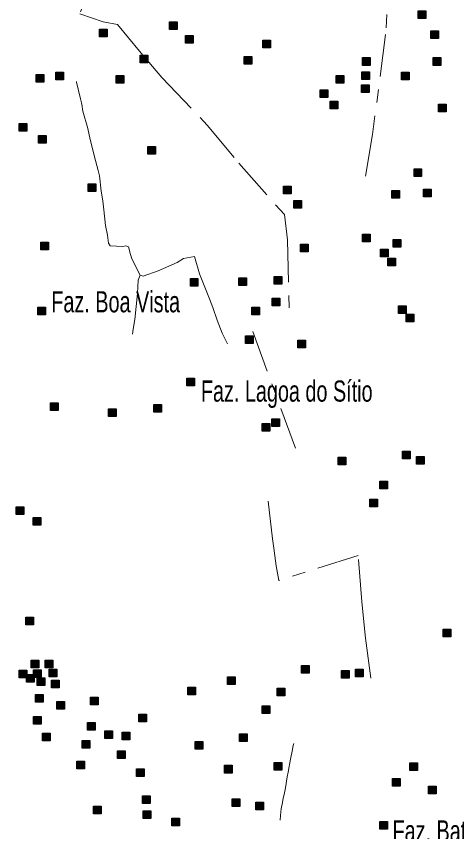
# Model space of a CAD drawing. Extents: x 445.4 to 500, y 8728.7 to 8784.
# Drawn here: x 480.51 to 483.85, y 8757.8 to 8763.96 of the extents above; entities that cross this region are included whole.
import ezdxf

# ---------------------------------------------------------------- set-up
doc = ezdxf.new("R2010")
doc.units = 0
doc.header["$LTSCALE"] = 0.064
doc.linetypes.add('DOT_DASHED', pattern=[7.7, 5, -1.2, 0.3, -1.2])
doc.layers.add('2', color=7, linetype='Continuous', lineweight=25)
doc.layers.add('22', color=7, linetype='DOT_DASHED', lineweight=13)
doc.layers.add('61', color=7, linetype='Continuous')

msp = doc.modelspace()

# ---------------------------------------------------------------- hatches: boundary and pattern name
at = {"layer": '2'}
for points in [[(483.5536, 8764.0015), (483.6116, 8764.0015), (483.6116, 8763.9435), (483.5536, 8763.9435)], [(481.6712, 8763.92), (481.7292, 8763.92), (481.7292, 8763.862), (481.6712, 8763.862)], [(481.143, 8763.8651), (481.201, 8763.8651), (481.201, 8763.8071), (481.143, 8763.8071)], [(483.6486, 8763.8521), (483.7066, 8763.8521), (483.7066, 8763.7941), (483.6486, 8763.7941)], [(481.7934, 8763.8159), (481.8514, 8763.8159), (481.8514, 8763.7579), (481.7934, 8763.7579)], [(482.3771, 8763.7797), (482.4351, 8763.7797), (482.4351, 8763.7217), (482.3771, 8763.7217)], [(481.4495, 8763.6665), (481.5075, 8763.6665), (481.5075, 8763.6085), (481.4495, 8763.6085)], [(482.2368, 8763.6574), (482.2948, 8763.6574), (482.2948, 8763.5994), (482.2368, 8763.5994)], [(483.1328, 8763.6484), (483.1908, 8763.6484), (483.1908, 8763.5904), (483.1328, 8763.5904)], [(483.6667, 8763.6484), (483.7247, 8763.6484), (483.7247, 8763.5904), (483.6667, 8763.5904)], [(480.6621, 8763.5214), (480.7201, 8763.5214), (480.7201, 8763.4634), (480.6621, 8763.4634)], [(480.8114, 8763.5395), (480.8694, 8763.5395), (480.8694, 8763.4815), (480.8114, 8763.4815)], [(481.2685, 8763.5143), (481.3265, 8763.5143), (481.3265, 8763.4563), (481.2685, 8763.4563)], [(482.9337, 8763.5143), (482.9917, 8763.5143), (482.9917, 8763.4563), (482.9337, 8763.4563)], [(483.1282, 8763.5415), (483.1862, 8763.5415), (483.1862, 8763.4835), (483.1282, 8763.4835)], [(483.4269, 8763.5391), (483.4849, 8763.5391), (483.4849, 8763.4811), (483.4269, 8763.4811)], [(482.8115, 8763.4056), (482.8695, 8763.4056), (482.8695, 8763.3476), (482.8115, 8763.3476)], [(483.1237, 8763.4419), (483.1817, 8763.4419), (483.1817, 8763.3839), (483.1237, 8763.3839)], [(482.8884, 8763.3196), (482.9464, 8763.3196), (482.9464, 8763.2616), (482.8884, 8763.2616)], [(483.7074, 8763.297), (483.7654, 8763.297), (483.7654, 8763.239), (483.7074, 8763.239)], [(480.5354, 8763.1501), (480.5934, 8763.1501), (480.5934, 8763.0921), (480.5354, 8763.0921)], [(480.6802, 8763.0596), (480.7382, 8763.0596), (480.7382, 8763.0016), (480.6802, 8763.0016)], [(481.5083, 8762.9755), (481.5663, 8762.9755), (481.5663, 8762.9175), (481.5083, 8762.9175)], [(483.5219, 8762.808), (483.5799, 8762.808), (483.5799, 8762.75), (483.5219, 8762.75)], [(481.0558, 8762.6948), (481.1138, 8762.6948), (481.1138, 8762.6368), (481.0558, 8762.6368)], [(482.5355, 8762.6767), (482.5935, 8762.6767), (482.5935, 8762.6187), (482.5355, 8762.6187)], [(483.5943, 8762.6541), (483.6523, 8762.6541), (483.6523, 8762.5961), (483.5943, 8762.5961)], [(483.3545, 8762.645), (483.4125, 8762.645), (483.4125, 8762.587), (483.3545, 8762.587)], [(482.6124, 8762.5681), (482.6704, 8762.5681), (482.6704, 8762.5101), (482.6124, 8762.5101)], [(483.1328, 8762.3145), (483.1908, 8762.3145), (483.1908, 8762.2565), (483.1328, 8762.2565)], [(480.6983, 8762.2537), (480.7563, 8762.2537), (480.7563, 8762.1957), (480.6983, 8762.1957)], [(482.6622, 8762.2376), (482.7202, 8762.2376), (482.7202, 8762.1796), (482.6622, 8762.1796)], [(483.3635, 8762.2738), (483.4215, 8762.2738), (483.4215, 8762.2158), (483.3635, 8762.2158)], [(483.2685, 8762.2013), (483.3265, 8762.2013), (483.3265, 8762.1433), (483.2685, 8762.1433)], [(483.3228, 8762.1334), (483.3808, 8762.1334), (483.3808, 8762.0754), (483.3228, 8762.0754)], [(481.8296, 8761.9795), (481.8876, 8761.9795), (481.8876, 8761.9215), (481.8296, 8761.9215)], [(482.1961, 8761.984), (482.2541, 8761.984), (482.2541, 8761.926), (482.1961, 8761.926)], [(482.4641, 8761.9945), (482.5221, 8761.9945), (482.5221, 8761.9365), (482.4641, 8761.9365)], [(482.4495, 8761.8301), (482.5075, 8761.8301), (482.5075, 8761.7721), (482.4495, 8761.7721)], [(480.6757, 8761.763), (480.7337, 8761.763), (480.7337, 8761.705), (480.6757, 8761.705)], [(482.2944, 8761.7629), (482.3524, 8761.7629), (482.3524, 8761.7049), (482.2944, 8761.7049)], [(483.4043, 8761.7712), (483.4623, 8761.7712), (483.4623, 8761.7132), (483.4043, 8761.7132)], [(483.4631, 8761.7079), (483.5211, 8761.7079), (483.5211, 8761.6499), (483.4631, 8761.6499)], [(482.2459, 8761.5449), (482.3039, 8761.5449), (482.3039, 8761.4869), (482.2459, 8761.4869)], [(482.6441, 8761.5132), (482.7021, 8761.5132), (482.7021, 8761.4552), (482.6441, 8761.4552)], [(481.8031, 8761.2258), (481.8611, 8761.2258), (481.8611, 8761.1678), (481.8031, 8761.1678)], [(480.7707, 8761.0386), (480.8287, 8761.0386), (480.8287, 8760.9806), (480.7707, 8760.9806)], [(481.2096, 8760.9943), (481.2676, 8760.9943), (481.2676, 8760.9363), (481.2096, 8760.9363)], [(481.5535, 8761.026), (481.6115, 8761.026), (481.6115, 8760.968), (481.5535, 8760.968)], [(482.3726, 8760.8811), (482.4306, 8760.8811), (482.4306, 8760.8231), (482.3726, 8760.8231)], [(482.445, 8760.9173), (482.503, 8760.9173), (482.503, 8760.8593), (482.445, 8760.8593)], [(482.9472, 8760.6276), (483.0052, 8760.6276), (483.0052, 8760.5696), (482.9472, 8760.5696)], [(483.4359, 8760.6728), (483.4939, 8760.6728), (483.4939, 8760.6148), (483.4359, 8760.6148)], [(483.54, 8760.6321), (483.598, 8760.6321), (483.598, 8760.5741), (483.54, 8760.5741)], [(483.264, 8760.4465), (483.322, 8760.4465), (483.322, 8760.3885), (483.264, 8760.3885)], [(483.1871, 8760.3106), (483.2451, 8760.3106), (483.2451, 8760.2526), (483.1871, 8760.2526)], [(480.5128, 8760.2526), (480.5708, 8760.2526), (480.5708, 8760.1946), (480.5128, 8760.1946)], [(480.6395, 8760.1711), (480.6975, 8760.1711), (480.6975, 8760.1131), (480.6395, 8760.1131)], [(480.5852, 8759.4178), (480.6432, 8759.4178), (480.6432, 8759.3598), (480.5852, 8759.3598)], [(483.7436, 8759.3282), (483.8016, 8759.3282), (483.8016, 8759.2702), (483.7436, 8759.2702)], [(480.6259, 8759.0918), (480.6839, 8759.0918), (480.6839, 8759.0338), (480.6259, 8759.0338)], [(480.73, 8759.0918), (480.788, 8759.0918), (480.788, 8759.0338), (480.73, 8759.0338)], [(480.5354, 8759.0184), (480.5934, 8759.0184), (480.5934, 8758.9604), (480.5354, 8758.9604)], [(480.644, 8759.0193), (480.702, 8759.0193), (480.702, 8758.9613), (480.644, 8758.9613)], [(480.7617, 8759.0239), (480.8197, 8759.0239), (480.8197, 8758.9659), (480.7617, 8758.9659)], [(482.6712, 8759.052), (482.7292, 8759.052), (482.7292, 8758.994), (482.6712, 8758.994)], [(482.9744, 8759.0158), (483.0324, 8759.0158), (483.0324, 8758.9578), (482.9744, 8758.9578)], [(483.0785, 8759.0248), (483.1365, 8759.0248), (483.1365, 8758.9668), (483.0785, 8758.9668)], [(480.5908, 8758.9843), (480.6488, 8758.9843), (480.6488, 8758.9263), (480.5908, 8758.9263)], [(480.6712, 8758.9605), (480.7292, 8758.9605), (480.7292, 8758.9025), (480.6712, 8758.9025)], [(482.1101, 8758.966), (482.1681, 8758.966), (482.1681, 8758.908), (482.1101, 8758.908)], [(480.7798, 8758.9424), (480.8378, 8758.9424), (480.8378, 8758.8844), (480.7798, 8758.8844)], [(480.6576, 8758.8337), (480.7156, 8758.8337), (480.7156, 8758.7757), (480.6576, 8758.7757)], [(481.8115, 8758.889), (481.8695, 8758.889), (481.8695, 8758.831), (481.8115, 8758.831)], [(482.4857, 8758.88), (482.5437, 8758.88), (482.5437, 8758.822), (482.4857, 8758.822)], [(480.8205, 8758.7812), (480.8785, 8758.7812), (480.8785, 8758.7232), (480.8205, 8758.7232)], [(481.0739, 8758.8121), (481.1319, 8758.8121), (481.1319, 8758.7541), (481.0739, 8758.7541)], [(482.3726, 8758.7487), (482.4306, 8758.7487), (482.4306, 8758.6907), (482.3726, 8758.6907)], [(480.644, 8758.668), (480.702, 8758.668), (480.702, 8758.61), (480.644, 8758.61)], [(481.4404, 8758.6853), (481.4984, 8758.6853), (481.4984, 8758.6273), (481.4404, 8758.6273)], [(481.0513, 8758.6219), (481.1093, 8758.6219), (481.1093, 8758.5639), (481.0513, 8758.5639)], [(480.7119, 8758.5412), (480.7699, 8758.5412), (480.7699, 8758.4832), (480.7119, 8758.4832)], [(481.1825, 8758.5585), (481.2405, 8758.5585), (481.2405, 8758.5005), (481.1825, 8758.5005)], [(481.3137, 8758.5495), (481.3717, 8758.5495), (481.3717, 8758.4915), (481.3137, 8758.4915)], [(482.2006, 8758.5359), (482.2586, 8758.5359), (482.2586, 8758.4779), (482.2006, 8758.4779)], [(481.0105, 8758.4861), (481.0685, 8758.4861), (481.0685, 8758.4281), (481.0105, 8758.4281)], [(481.8658, 8758.4788), (481.9238, 8758.4788), (481.9238, 8758.4208), (481.8658, 8758.4208)], [(481.2775, 8758.4064), (481.3355, 8758.4064), (481.3355, 8758.3484), (481.2775, 8758.3484)], [(480.9698, 8758.3294), (481.0278, 8758.3294), (481.0278, 8758.2714), (480.9698, 8758.2714)], [(482.0875, 8758.2977), (482.1455, 8758.2977), (482.1455, 8758.2397), (482.0875, 8758.2397)], [(482.4631, 8758.3203), (482.5211, 8758.3203), (482.5211, 8758.2623), (482.4631, 8758.2623)], [(483.4902, 8758.3158), (483.5482, 8758.3158), (483.5482, 8758.2578), (483.4902, 8758.2578)], [(481.4223, 8758.2705), (481.4803, 8758.2705), (481.4803, 8758.2125), (481.4223, 8758.2125)], [(483.359, 8758.1981), (483.417, 8758.1981), (483.417, 8758.1401), (483.359, 8758.1401)], [(483.6305, 8758.1392), (483.6885, 8758.1392), (483.6885, 8758.0812), (483.6305, 8758.0812)], [(481.4676, 8758.0668), (481.5256, 8758.0668), (481.5256, 8758.0088), (481.4676, 8758.0088)], [(482.1463, 8758.0442), (482.2043, 8758.0442), (482.2043, 8757.9862), (482.1463, 8757.9862)], [(481.0965, 8757.9898), (481.1545, 8757.9898), (481.1545, 8757.9318), (481.0965, 8757.9318)], [(482.3257, 8758.0192), (482.3837, 8758.0192), (482.3837, 8757.9612), (482.3257, 8757.9612)], [(481.4721, 8757.9536), (481.5301, 8757.9536), (481.5301, 8757.8956), (481.4721, 8757.8956)], [(481.6893, 8757.8993), (481.7473, 8757.8993), (481.7473, 8757.8413), (481.6893, 8757.8413)], [(483.264, 8757.8721), (483.322, 8757.8721), (483.322, 8757.8141), (483.264, 8757.8141)]]:
    msp.add_hatch(color=256, dxfattribs=at).paths.add_polyline_path(points)

# ---------------------------------------------------------------- linework, layer by layer
for points in [[(483.5536, 8764.0015), (483.6116, 8764.0015), (483.6116, 8763.9435), (483.5536, 8763.9435)], [(481.6712, 8763.92), (481.7292, 8763.92), (481.7292, 8763.862), (481.6712, 8763.862)], [(481.143, 8763.8651), (481.201, 8763.8651), (481.201, 8763.8071), (481.143, 8763.8071)], [(483.6486, 8763.8521), (483.7066, 8763.8521), (483.7066, 8763.7941), (483.6486, 8763.7941)], [(481.7934, 8763.8159), (481.8514, 8763.8159), (481.8514, 8763.7579), (481.7934, 8763.7579)], [(482.3771, 8763.7797), (482.4351, 8763.7797), (482.4351, 8763.7217), (482.3771, 8763.7217)], [(481.4495, 8763.6665), (481.5075, 8763.6665), (481.5075, 8763.6085), (481.4495, 8763.6085)], [(482.2368, 8763.6574), (482.2948, 8763.6574), (482.2948, 8763.5994), (482.2368, 8763.5994)], [(483.1328, 8763.6484), (483.1908, 8763.6484), (483.1908, 8763.5904), (483.1328, 8763.5904)], [(483.6667, 8763.6484), (483.7247, 8763.6484), (483.7247, 8763.5904), (483.6667, 8763.5904)], [(480.6621, 8763.5214), (480.7201, 8763.5214), (480.7201, 8763.4634), (480.6621, 8763.4634)], [(480.8114, 8763.5395), (480.8694, 8763.5395), (480.8694, 8763.4815), (480.8114, 8763.4815)], [(481.2685, 8763.5143), (481.3265, 8763.5143), (481.3265, 8763.4563), (481.2685, 8763.4563)], [(482.9337, 8763.5143), (482.9917, 8763.5143), (482.9917, 8763.4563), (482.9337, 8763.4563)], [(483.1282, 8763.5415), (483.1862, 8763.5415), (483.1862, 8763.4835), (483.1282, 8763.4835)], [(483.4269, 8763.5391), (483.4849, 8763.5391), (483.4849, 8763.4811), (483.4269, 8763.4811)], [(482.8115, 8763.4056), (482.8695, 8763.4056), (482.8695, 8763.3476), (482.8115, 8763.3476)], [(483.1237, 8763.4419), (483.1817, 8763.4419), (483.1817, 8763.3839), (483.1237, 8763.3839)], [(482.8884, 8763.3196), (482.9464, 8763.3196), (482.9464, 8763.2616), (482.8884, 8763.2616)], [(483.7074, 8763.297), (483.7654, 8763.297), (483.7654, 8763.239), (483.7074, 8763.239)], [(480.5354, 8763.1501), (480.5934, 8763.1501), (480.5934, 8763.0921), (480.5354, 8763.0921)], [(480.6802, 8763.0596), (480.7382, 8763.0596), (480.7382, 8763.0016), (480.6802, 8763.0016)], [(481.5083, 8762.9755), (481.5663, 8762.9755), (481.5663, 8762.9175), (481.5083, 8762.9175)], [(483.5219, 8762.808), (483.5799, 8762.808), (483.5799, 8762.75), (483.5219, 8762.75)], [(481.0558, 8762.6948), (481.1138, 8762.6948), (481.1138, 8762.6368), (481.0558, 8762.6368)], [(482.5355, 8762.6767), (482.5935, 8762.6767), (482.5935, 8762.6187), (482.5355, 8762.6187)], [(483.5943, 8762.6541), (483.6523, 8762.6541), (483.6523, 8762.5961), (483.5943, 8762.5961)], [(483.3545, 8762.645), (483.4125, 8762.645), (483.4125, 8762.587), (483.3545, 8762.587)], [(482.6124, 8762.5681), (482.6704, 8762.5681), (482.6704, 8762.5101), (482.6124, 8762.5101)], [(483.1328, 8762.3145), (483.1908, 8762.3145), (483.1908, 8762.2565), (483.1328, 8762.2565)], [(480.6983, 8762.2537), (480.7563, 8762.2537), (480.7563, 8762.1957), (480.6983, 8762.1957)], [(482.6622, 8762.2376), (482.7202, 8762.2376), (482.7202, 8762.1796), (482.6622, 8762.1796)], [(483.3635, 8762.2738), (483.4215, 8762.2738), (483.4215, 8762.2158), (483.3635, 8762.2158)], [(483.2685, 8762.2013), (483.3265, 8762.2013), (483.3265, 8762.1433), (483.2685, 8762.1433)], [(483.3228, 8762.1334), (483.3808, 8762.1334), (483.3808, 8762.0754), (483.3228, 8762.0754)], [(481.8296, 8761.9795), (481.8876, 8761.9795), (481.8876, 8761.9215), (481.8296, 8761.9215)], [(482.1961, 8761.984), (482.2541, 8761.984), (482.2541, 8761.926), (482.1961, 8761.926)], [(482.4641, 8761.9945), (482.5221, 8761.9945), (482.5221, 8761.9365), (482.4641, 8761.9365)], [(482.4495, 8761.8301), (482.5075, 8761.8301), (482.5075, 8761.7721), (482.4495, 8761.7721)], [(480.6757, 8761.763), (480.7337, 8761.763), (480.7337, 8761.705), (480.6757, 8761.705)], [(482.2944, 8761.7629), (482.3524, 8761.7629), (482.3524, 8761.7049), (482.2944, 8761.7049)], [(483.4043, 8761.7712), (483.4623, 8761.7712), (483.4623, 8761.7132), (483.4043, 8761.7132)], [(483.4631, 8761.7079), (483.5211, 8761.7079), (483.5211, 8761.6499), (483.4631, 8761.6499)], [(482.2459, 8761.5449), (482.3039, 8761.5449), (482.3039, 8761.4869), (482.2459, 8761.4869)], [(482.6441, 8761.5132), (482.7021, 8761.5132), (482.7021, 8761.4552), (482.6441, 8761.4552)], [(481.8031, 8761.2258), (481.8611, 8761.2258), (481.8611, 8761.1678), (481.8031, 8761.1678)], [(480.7707, 8761.0386), (480.8287, 8761.0386), (480.8287, 8760.9806), (480.7707, 8760.9806)], [(481.2096, 8760.9943), (481.2676, 8760.9943), (481.2676, 8760.9363), (481.2096, 8760.9363)], [(481.5535, 8761.026), (481.6115, 8761.026), (481.6115, 8760.968), (481.5535, 8760.968)], [(482.3726, 8760.8811), (482.4306, 8760.8811), (482.4306, 8760.8231), (482.3726, 8760.8231)], [(482.445, 8760.9173), (482.503, 8760.9173), (482.503, 8760.8593), (482.445, 8760.8593)], [(482.9472, 8760.6276), (483.0052, 8760.6276), (483.0052, 8760.5696), (482.9472, 8760.5696)], [(483.4359, 8760.6728), (483.4939, 8760.6728), (483.4939, 8760.6148), (483.4359, 8760.6148)], [(483.54, 8760.6321), (483.598, 8760.6321), (483.598, 8760.5741), (483.54, 8760.5741)], [(483.264, 8760.4465), (483.322, 8760.4465), (483.322, 8760.3885), (483.264, 8760.3885)], [(483.1871, 8760.3106), (483.2451, 8760.3106), (483.2451, 8760.2526), (483.1871, 8760.2526)], [(480.5128, 8760.2526), (480.5708, 8760.2526), (480.5708, 8760.1946), (480.5128, 8760.1946)], [(480.6395, 8760.1711), (480.6975, 8760.1711), (480.6975, 8760.1131), (480.6395, 8760.1131)], [(480.5852, 8759.4178), (480.6432, 8759.4178), (480.6432, 8759.3598), (480.5852, 8759.3598)], [(483.7436, 8759.3282), (483.8016, 8759.3282), (483.8016, 8759.2702), (483.7436, 8759.2702)], [(480.6259, 8759.0918), (480.6839, 8759.0918), (480.6839, 8759.0338), (480.6259, 8759.0338)], [(480.73, 8759.0918), (480.788, 8759.0918), (480.788, 8759.0338), (480.73, 8759.0338)], [(480.5354, 8759.0184), (480.5934, 8759.0184), (480.5934, 8758.9604), (480.5354, 8758.9604)], [(480.644, 8759.0193), (480.702, 8759.0193), (480.702, 8758.9613), (480.644, 8758.9613)], [(480.7617, 8759.0239), (480.8197, 8759.0239), (480.8197, 8758.9659), (480.7617, 8758.9659)], [(482.6712, 8759.052), (482.7292, 8759.052), (482.7292, 8758.994), (482.6712, 8758.994)], [(482.9744, 8759.0158), (483.0324, 8759.0158), (483.0324, 8758.9578), (482.9744, 8758.9578)], [(483.0785, 8759.0248), (483.1365, 8759.0248), (483.1365, 8758.9668), (483.0785, 8758.9668)], [(480.5908, 8758.9843), (480.6488, 8758.9843), (480.6488, 8758.9263), (480.5908, 8758.9263)], [(480.6712, 8758.9605), (480.7292, 8758.9605), (480.7292, 8758.9025), (480.6712, 8758.9025)], [(482.1101, 8758.966), (482.1681, 8758.966), (482.1681, 8758.908), (482.1101, 8758.908)], [(480.7798, 8758.9424), (480.8378, 8758.9424), (480.8378, 8758.8844), (480.7798, 8758.8844)], [(480.6576, 8758.8337), (480.7156, 8758.8337), (480.7156, 8758.7757), (480.6576, 8758.7757)], [(481.8115, 8758.889), (481.8695, 8758.889), (481.8695, 8758.831), (481.8115, 8758.831)], [(482.4857, 8758.88), (482.5437, 8758.88), (482.5437, 8758.822), (482.4857, 8758.822)], [(480.8205, 8758.7812), (480.8785, 8758.7812), (480.8785, 8758.7232), (480.8205, 8758.7232)], [(481.0739, 8758.8121), (481.1319, 8758.8121), (481.1319, 8758.7541), (481.0739, 8758.7541)], [(482.3726, 8758.7487), (482.4306, 8758.7487), (482.4306, 8758.6907), (482.3726, 8758.6907)], [(480.644, 8758.668), (480.702, 8758.668), (480.702, 8758.61), (480.644, 8758.61)], [(481.4404, 8758.6853), (481.4984, 8758.6853), (481.4984, 8758.6273), (481.4404, 8758.6273)], [(481.0513, 8758.6219), (481.1093, 8758.6219), (481.1093, 8758.5639), (481.0513, 8758.5639)], [(480.7119, 8758.5412), (480.7699, 8758.5412), (480.7699, 8758.4832), (480.7119, 8758.4832)], [(481.1825, 8758.5585), (481.2405, 8758.5585), (481.2405, 8758.5005), (481.1825, 8758.5005)], [(481.3137, 8758.5495), (481.3717, 8758.5495), (481.3717, 8758.4915), (481.3137, 8758.4915)], [(482.2006, 8758.5359), (482.2586, 8758.5359), (482.2586, 8758.4779), (482.2006, 8758.4779)], [(481.0105, 8758.4861), (481.0685, 8758.4861), (481.0685, 8758.4281), (481.0105, 8758.4281)], [(481.8658, 8758.4788), (481.9238, 8758.4788), (481.9238, 8758.4208), (481.8658, 8758.4208)], [(481.2775, 8758.4064), (481.3355, 8758.4064), (481.3355, 8758.3484), (481.2775, 8758.3484)], [(480.9698, 8758.3294), (481.0278, 8758.3294), (481.0278, 8758.2714), (480.9698, 8758.2714)], [(482.0875, 8758.2977), (482.1455, 8758.2977), (482.1455, 8758.2397), (482.0875, 8758.2397)], [(482.4631, 8758.3203), (482.5211, 8758.3203), (482.5211, 8758.2623), (482.4631, 8758.2623)], [(483.4902, 8758.3158), (483.5482, 8758.3158), (483.5482, 8758.2578), (483.4902, 8758.2578)], [(481.4223, 8758.2705), (481.4803, 8758.2705), (481.4803, 8758.2125), (481.4223, 8758.2125)], [(483.359, 8758.1981), (483.417, 8758.1981), (483.417, 8758.1401), (483.359, 8758.1401)], [(483.6305, 8758.1392), (483.6885, 8758.1392), (483.6885, 8758.0812), (483.6305, 8758.0812)], [(481.4676, 8758.0668), (481.5256, 8758.0668), (481.5256, 8758.0088), (481.4676, 8758.0088)], [(482.1463, 8758.0442), (482.2043, 8758.0442), (482.2043, 8757.9862), (482.1463, 8757.9862)], [(481.0965, 8757.9898), (481.1545, 8757.9898), (481.1545, 8757.9318), (481.0965, 8757.9318)], [(482.3257, 8758.0192), (482.3837, 8758.0192), (482.3837, 8757.9612), (482.3257, 8757.9612)], [(481.4721, 8757.9536), (481.5301, 8757.9536), (481.5301, 8757.8956), (481.4721, 8757.8956)], [(481.6893, 8757.8993), (481.7473, 8757.8993), (481.7473, 8757.8413), (481.6893, 8757.8413)], [(483.264, 8757.8721), (483.322, 8757.8721), (483.322, 8757.8141), (483.264, 8757.8141)]]:
    msp.add_lwpolyline(points, close=True, dxfattribs=at)
at = {"layer": '22'}
msp.add_line((482.6254, 8760.6949), (482.2954, 8761.594), dxfattribs=at)
for points in [[(483.17, 8764.8294), (483.3433, 8764.3939), (483.3075, 8763.8242), (483.208, 8763.0675), (483.1399, 8762.6614)], [(481.185, 8764.48), (480.9932, 8763.9797), (481.1704, 8763.9201), (481.279, 8763.8984), (481.4448, 8763.6968), (481.6132, 8763.4981), (481.9577, 8763.1388), (482.197, 8762.8515), (482.5414, 8762.4616), (482.5644, 8762.2705), (482.5773, 8761.756)], [(481.0156, 8763.2428), (481.0129, 8763.2556), (481.011, 8763.2825), (481.0072, 8763.3075), (480.9995, 8763.3383), (480.9687, 8763.4634), (480.9679, 8763.4678)], [(481.4512, 8762.0028), (481.3874, 8762.1267), (481.3761, 8762.1605), (481.3611, 8762.2169), (481.3423, 8762.2244), (481.3197, 8762.2207), (481.2221, 8762.2244), (481.2108, 8762.247), (481.2033, 8762.3071), (481.1882, 8762.3786), (481.1755, 8762.4988), (481.1669, 8762.5662), (481.1548, 8762.638), (481.1427, 8762.7555), (481.1319, 8762.7959), (481.1131, 8762.8711), (481.0726, 8763.0293), (481.053, 8763.1117), (481.0156, 8763.2428)], [(481.4512, 8762.0028), (481.4738, 8761.9951), (481.5865, 8762.0364), (481.7293, 8762.1003), (481.7782, 8762.1304), (481.8608, 8762.1455), (481.8984, 8762.0139), (481.9735, 8761.8259), (481.9998, 8761.7582), (482.0337, 8761.6642), (482.0712, 8761.5665), (482.1109, 8761.4839)], [(481.4512, 8762.0028), (481.4357, 8761.9668), (481.43, 8761.8644), (481.4206, 8761.7677), (481.4092, 8761.6691), (481.3978, 8761.5951), (481.3931, 8761.5578)], [(483.195, 8758.9577), (483.1558, 8759.2593), (483.1273, 8759.5344), (483.0988, 8759.8855), (482.5002, 8759.6958), (482.4778, 8759.805), (482.4604, 8759.9402), (482.4502, 8760.0098), (482.4173, 8760.2957)], [(482.5085, 8757.8824), (482.5106, 8757.9173), (482.5174, 8757.969), (482.5271, 8758.0158), (482.5324, 8758.0485), (482.5388, 8758.0765), (482.5485, 8758.1287), (482.562, 8758.2109), (482.5694, 8758.2453), (482.5769, 8758.2877), (482.5803, 8758.3051), (482.5893, 8758.3566), (482.5997, 8758.4039), (482.6077, 8758.4488), (482.6126, 8758.4632)]]:
    msp.add_lwpolyline(points, dxfattribs=at)

# ---------------------------------------------------------------- texts
at = {"layer": '61', "width": 0.7}
for s, p in [('Faz. Boa Vista', (480.7779, 8761.7228)), ('Faz. Lagoa do Sítio', (481.9096, 8761.0475)), ('Faz. Batente de Pedra', (483.3595, 8757.7221))]:
    msp.add_text(s, height=0.16, dxfattribs=at).set_placement(p)

doc.saveas('drawing.dxf')
